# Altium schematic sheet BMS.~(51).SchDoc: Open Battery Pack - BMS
size A3; Date: 26/03/2019; Author: Morgane Vallée - Samuel Lesueur; Revision: 1.0; SheetNumber: 1; SheetTotal: 3
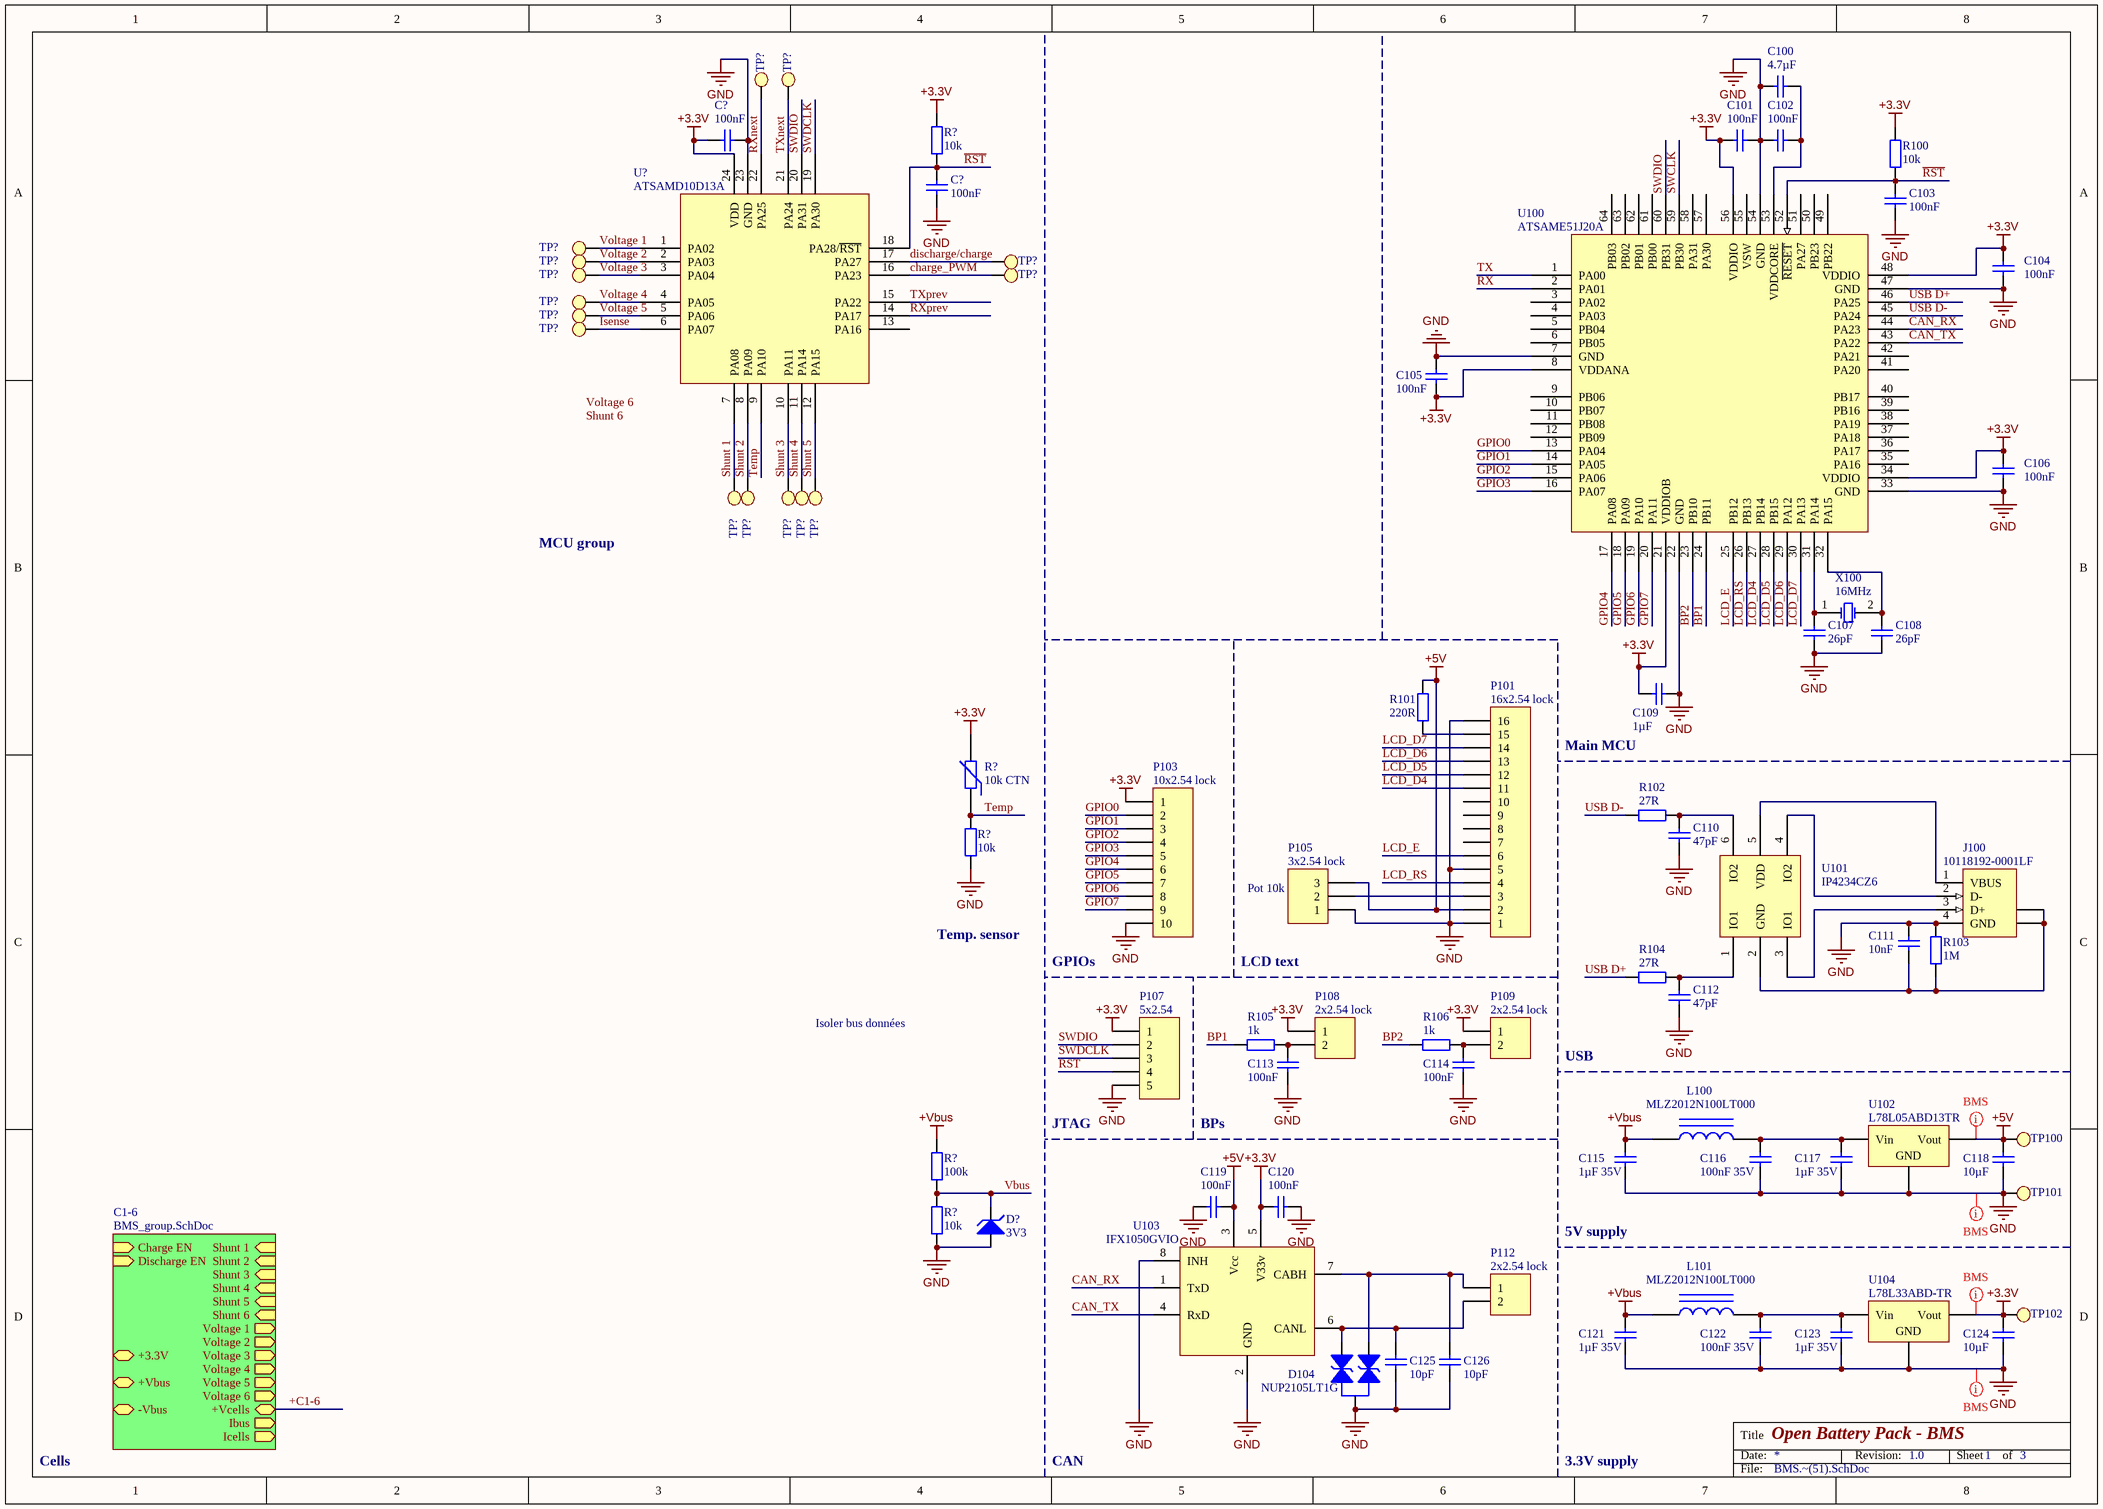
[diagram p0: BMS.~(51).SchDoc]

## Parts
(Parts that share a designator on the sheet are numbered #1, #2 ... from top to bottom, then left to right.)
C100  4.7µF  [C0603]
C101  100nF  [C0603]
C102  100nF  [C0603]
C103  100nF  [C0603]
C104  100nF  [C0603]
C105  100nF  [C0603]
C106  100nF  [C0603]
C107  26pF  [C0603]
C108  26pF  [C0603]
C109  1µF  [C0603]
C110  47pF  [C0603]
C111  10nF  [C0603]
C112  47pF  [C0603]
C113  100nF  [C0603]
C114  100nF  [C0603]
C115  1µF 35V  [C0805]
C116  100nF 35V  [C0603]
C117  1µF 35V  [C0805]
C118  10µF  [C0603]
C119  100nF  [C0603]
C120  100nF  [C0603]
C121  1µF 35V  [C0805]
C122  100nF 35V  [C0603]
C123  1µF 35V  [C0805]
C124  10µF  [C0603]
C125  10pF  [C0603]
C126  10pF  [C0603]
C?#1  100nF  [C0603]
C?#2  100nF  [C0603]
D104  NUP2105LT1G  [DIODES SOT-23-3]
D?  3V3  [DIODE-0.7]
J100  10118192-0001LF  [FCI USB 10118193-0001LF]
L100  MLZ2012N100LT000  [FER 0805/2012]
L101  MLZ2012N100LT000  [FER 0805/2012]
P101  16x2.54 lock  [HDR1X16]
P103  10x2.54 lock  [MOLEX KK 0022272101]
P105  3x2.54 lock  [MOLEX KK 0022272031]
P107  5x2.54  [HDR1X5]
P108  2x2.54 lock  [MOLEX KK 0022272021]
P109  2x2.54 lock  [MOLEX KK 0022272021]
P112  2x2.54 lock  [FCI 06-381-2PIN]
R100  10k  [R0603]
R101  220R  [R0603]
R102  27R  [R0603]
R103  1M  [R0603]
R104  27R  [R0603]
R105  1k  [R0603]
R106  1k  [R0603]
R?#1  10k  [R0603]
R?#2  10k CTN  [NTC 0402/1005]
R?#3  10k  [R0603]
R?#4  100k  [R0603]
R?#5  10k  [R0603]
TP100  Test Point  [Test Point]  (value not drawn)
TP101  Test Point  [Test Point]  (value not drawn)
TP102  Test Point  [Test Point]  (value not drawn)
TP?#1  Test Point  [Test Point]  (value not drawn)
TP?#2  Test Point  [Test Point]  (value not drawn)
TP?#3  Test Point  [Test Point]  (value not drawn)
TP?#4  Test Point  [Test Point]  (value not drawn)
TP?#5  Test Point  [Test Point]  (value not drawn)
TP?#6  Test Point  [Test Point]  (value not drawn)
TP?#7  Test Point  [Test Point]  (value not drawn)
TP?#8  Test Point  [Test Point]  (value not drawn)
TP?#9  Test Point  [Test Point]  (value not drawn)
TP?#10  Test Point  [Test Point]  (value not drawn)
TP?#11  Test Point  [Test Point]  (value not drawn)
TP?#12  Test Point  [Test Point]  (value not drawn)
TP?#13  Test Point  [Test Point]  (value not drawn)
TP?#14  Test Point  [Test Point]  (value not drawn)
TP?#15  Test Point  [Test Point]  (value not drawn)
U100  ATSAME51J20A  [TQFP-64N]
U101  IP4234CZ6  [VISHAY TSOP-6 MO-193C]
U102  L78L05ABD13TR  [ST SOIC-8N]
U103  IFX1050GVIO  [INFINEON SO-8]
U104  L78L33ABD-TR  [ST SOIC-8N]
U?  ATSAMD10D13A  [SMSC QFN-24 4x4MM]
X100  16MHz  [ABRACON ABLS]

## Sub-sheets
C1-6 = BMS_group.SchDoc: -Vbus, +Vbus, Shunt 1 (in), Shunt 2 (in), Shunt 3 (in), Shunt 4 (in), Shunt 5 (in), Shunt 6 (in), Voltage 1 (out), Voltage 2 (out), Voltage 3 (out), Voltage 4 (out), +3.3V, Voltage 5 (out), Voltage 6 (out), +Vcells, Charge EN (in), Discharge EN (in), Ibus (out), Icells (out)

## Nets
+3.3V: C101.2 C104.2 C105.1 C106.2 C109.2 C120.1 C124.1 C?#1.2 P103.1 P107.1 P108.1 P109.1 R100.2 R?#1.2 R?#2.2 TP102.1 U100.8(VDDANA) U100.21(VDDIOB) U100.34(VDDIO) U100.48(VDDIO) U100.56(VDDIO) U103.5(V33v) U104.3(Vout) U?.24(VDD)
+5V: C118.1 C119.2 P101.2 P105.3 R101.2 TP100.1 U102.3(Vout) U103.3(Vcc)
+Vbus: C115.1 C121.1 L100.1 L101.1 R?#4.1
GND: C100.2 C101.1 C102.2 C103.1 C104.1 C105.2 C106.1 C107.1 C108.1 C109.1 C110.1 C111.2 C112.1 C113.1 C114.1 C115.2 C116.2 C117.2 C118.2 C119.1 C120.2 C121.2 C122.2 C123.2 C124.2 C125.1 C126.1 C?#1.1 C?#2.1 D104.3 D?.1(A) J100.4(GND) P101.1 P101.5 P101.16 P103.10 P105.1 P107.5 R103.1 R?#3.2 R?#5.2 TP101.1 U100.7(GND) U100.22(GND) U100.33(GND) U100.47(GND) U100.54(GND) U102.2(GND) U103.2(GND) U103.8(INH) U104.2(GND) U?.23(GND)
BP1: R105.1 U100.24(PB11)
BP2: R106.1 U100.23(PB10)
CAN_RX: U100.44(PA23) U103.1(TxD)
CAN_TX: U100.43(PA22) U103.4(RxD)
charge_PWM: TP?#7.1 U?.16(PA23)
discharge/charge: TP?#5.1 U?.17(PA27)
GPIO0: P103.2 U100.13(PA04)
GPIO1: P103.3 U100.14(PA05)
GPIO2: P103.4 U100.15(PA06)
GPIO3: P103.5 U100.16(PA07)
GPIO4: P103.6 U100.17(PA08)
GPIO5: P103.7 U100.18(PA09)
GPIO6: P103.8 U100.19(PA10)
GPIO7: P103.9 U100.20(PA11)
Isense: TP?#10.1 U?.6(PA07)
LCD_D4: P101.11 U100.27(PB14)
LCD_D5: P101.12 U100.28(PB15)
LCD_D6: P101.13 U100.29(PA12)
LCD_D7: P101.14 U100.30(PA13)
LCD_E: P101.6 U100.25(PB12)
LCD_RS: P101.4 U100.26(PB13)
~{RST}: C103.2 C?#2.2 P107.4 R100.1 R?#1.1 U100.52(~{RESET}) U?.18(PA28/~{RST})
RX: U100.2(PA01)
RXnext: TP?#1.1 U?.22(PA25)
RXprev: U?.14(PA17)
Shunt 1: TP?#11.1 U?.7(PA08)
Shunt 2: TP?#12.1 U?.8(PA09)
Shunt 3: TP?#13.1 U?.10(PA11)
Shunt 4: TP?#14.1 U?.11(PA14)
Shunt 5: TP?#15.1 U?.12(PA15)
SWCLK: U100.59(PB30)
SWDCLK: P107.3 U?.19(PA30)
SWDIO: P107.2 U100.60(PB31) U?.20(PA31)
Temp: R?#2.1 R?#3.1 U?.9(PA10)
TX: U100.1(PA00)
TXnext: TP?#2.1 U?.21(PA24)
TXprev: U?.15(PA22)
USB D+: R104.1 U100.46(PA25)
USB D-: R102.1 U100.45(PA24)
Vbus: D?.2(K) R?#4.2 R?#5.1
Voltage 1: TP?#3.1 U?.1(PA02)
Voltage 2: TP?#4.1 U?.2(PA03)
Voltage 3: TP?#6.1 U?.3(PA04)
Voltage 4: TP?#8.1 U?.4(PA05)
Voltage 5: TP?#9.1 U?.5(PA06)
NetC100_1: C100.1 C102.1 U100.53(VDDCORE)
NetC107_2: C107.2 U100.31(PA14) X100.1(OSC1)
NetC108_2: C108.2 U100.32(PA15) X100.2(OSC2)
NetC110_2: C110.2 R102.2 U101.6(IO2)
NetC111_1: C111.1 J100.5(SHLD) J100.6(SHLD) R103.2 U101.2(GND)
NetC112_2: C112.2 R104.2 U101.1(IO1)
NetC113_2: C113.2 P108.2 R105.2
NetC114_2: C114.2 P109.2 R106.2
NetC116_1: C116.1 C117.1 L100.2 U102.1(Vin)
NetC122_1: C122.1 C123.1 L101.2 U104.1(Vin)
NetC125_2: C125.2 D104.2 P112.2 U103.6(CANL)
NetC126_2: C126.2 D104.1 P112.1 U103.7(CABH)
NetJ100_1: J100.1(VBUS) U101.5(VDD)
NetJ100_2: J100.2(D-) U101.4(IO2)
NetJ100_3: J100.3(D+) U101.3(IO1)
NetP101_3: P101.3 P105.2
NetP101_15: P101.15 R101.1

Not connected (* = marked no-connect by the designer): P101 7 8 9 10; U100 3(PA02) 4(PA03) 5(PB04) 6(PB05) 9(PB06) 10(PB07) 11(PB08) 12(PB09) 35(PA16) 36(PA17) 37(PA18) 38(PA19) 39(PB16) 40(PB17) 41(PA20) 42(PA21) 49(PB22) 50(PB23) 51(PA27) 55(VSW) 57(PA30) 58(PA31) 61(PB00) 62(PB01) 63(PB02) 64(PB03); U? 13(PA16)

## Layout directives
net class BMS: +3.3V, +5V, GND

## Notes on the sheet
- MCU group
- Main MCU
- (near P105) Pot 10k
- Temp. sensor
- GPIOs
- LCD text
- Isoler bus données
- JTAG
- BPs
- USB
- 5V supply
- Cells
- CAN
- 3.3V supply
- Labels drawn without touching a wire or pin: Shunt 6, Voltage 6

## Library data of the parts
C100-C126 C?#1 C?#2 = Cap: Capacitor
D104 = Dual Line TVS
D? = Diode Zener
J100 = 1-353576-1: USB 1.1, Right Angle, SMT, A Type, Receptacle, 4 Position, White; pin to pad: 4>5 5>S 6>S
L100 L101 = Inductor Iron: Magnetic-Core Inductor
P101 = Header 16: Header, 16-Pin
P103 = Header 10: Header, 10-Pin
P105 = Header 3: Header, 3-Pin
P107 = Header 5: Header, 5-Pin
P108 P109 = Header 2: Header, 2-Pin
P112 = Header 2H: Header, 2-Pin, Right Angle
R100-R106 R?#1 R?#3-R?#5 = Res2: Resistor
R?#2 = Res Varistor: Varistor (Voltage-Sensitive Resistor)
U101 = IP4234CZ6: Single USB 2.0 ESD protection to IEC 61000-4-2 level 4
U102 U104 = Volt Reg: Voltage Regulator; pin to pad: 1>8 2>2+3+6+7 3>1
U103 = IFX1050GVIO: High Speed CAN-Transceiver
X100 = XTAL: Crystal Oscillator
